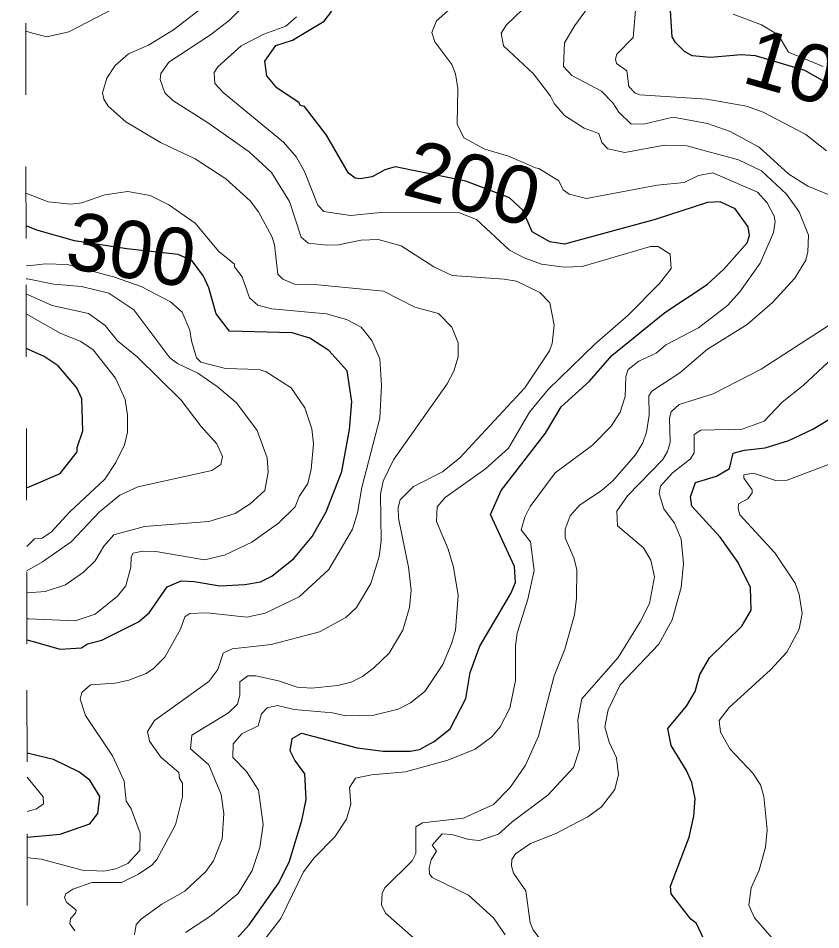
# Model space of a CAD drawing. Extents: x 474.5 to 500, y 7345.7 to 7373.4.
# Drawn here: x 474.546 to 475.665, y 7352.66 to 7353.931 of the extents above; entities that cross this region are included whole.
import ezdxf
from ezdxf.enums import TextEntityAlignment as Align

# ---------------------------------------------------------------- set-up
doc = ezdxf.new("R2010")
doc.units = 0
doc.header["$LTSCALE"] = 0.032
doc.linetypes.add('SHORT_DASHED', pattern=[2.7, 1.5, -1.2])
for name, color, linetype, lineweight in [('1', 7, 'Continuous', 25), ('2', 7, 'Continuous', 13), ('22', 7, 'SHORT_DASHED', 13)]:
    doc.layers.add(name, color=color, linetype=linetype, lineweight=lineweight)
doc.layers.add('61', color=7, linetype='Continuous')

msp = doc.modelspace()

# ---------------------------------------------------------------- linework, layer by layer
at = {"layer": '1'}
for points in [[(474.9417, 7352.8127), (474.9474, 7352.8417), (474.9458, 7352.8779), (474.9316, 7352.8968), (474.9253, 7352.9095), (474.9281, 7352.9267), (474.9413, 7352.9342), (475.0188, 7352.9139), (475.055, 7352.9091), (475.0929, 7352.9091), (475.1056, 7352.9116), (475.1259, 7352.9225), (475.1484, 7352.9402), (475.17, 7352.9825), (475.1763, 7353.0188), (475.1898, 7353.0555), (475.233, 7353.1292), (475.2393, 7353.1442), (475.2382, 7353.1668), (475.2045, 7353.2393), (475.2193, 7353.2725), (475.2811, 7353.3524), (475.3033, 7353.3893), (475.3426, 7353.4247), (475.374, 7353.4609), (475.4476, 7353.5207), (475.5065, 7353.5598), (475.53, 7353.581), (475.5625, 7353.6177), (475.5656, 7353.6279), (475.5641, 7353.6401), (475.5457, 7353.6653), (475.5247, 7353.6748), (475.5074, 7353.674), (475.4343, 7353.6502), (475.308, 7353.6159), (475.2873, 7353.6191), (475.2627, 7353.633), (475.2496, 7353.663), (475.2311, 7353.6803), (475.1702, 7353.7036), (475.0715, 7353.7234), (475.0575, 7353.7195), (475.0396, 7353.7099), (475.0227, 7353.7069), (475.0158, 7353.7078), (475.0068, 7353.7146), (474.976, 7353.7677), (474.9452, 7353.8079), (474.9394, 7353.8092), (474.9377, 7353.8129), (474.9065, 7353.8339), (474.8926, 7353.8502), (474.89, 7353.8708), (474.9054, 7353.8927), (474.9285, 7353.9), (474.9727, 7353.9268), (474.9836, 7353.9404)], [(475.6815, 7353.836), (475.6429, 7353.8577), (475.5739, 7353.8781), (475.5541, 7353.8798), (475.5114, 7353.876), (475.4857, 7353.8782), (475.475, 7353.8844), (475.4624, 7353.8969), (475.4579, 7353.9049), (475.4556, 7353.941)], [(474.5581, 7353.0644), (474.5671, 7353.0619), (474.6048, 7353.0513), (474.6342, 7353.0533), (474.6428, 7353.059), (474.6625, 7353.0641), (474.7138, 7353.0895), (474.7286, 7353.102), (474.7538, 7353.1381), (474.7733, 7353.1466), (474.7913, 7353.1459), (474.8274, 7353.1397), (474.8622, 7353.1414), (474.8839, 7353.1453), (474.8998, 7353.1533), (474.9303, 7353.1777), (474.9558, 7353.2084), (474.9755, 7353.2429), (474.9974, 7353.2992), (475.0081, 7353.3577), (475.0112, 7353.3959), (475.0049, 7353.4393), (474.9791, 7353.4676), (474.9525, 7353.4849), (474.9282, 7353.4922), (474.8406, 7353.4945), (474.8222, 7353.5186), (474.8121, 7353.5549), (474.8046, 7353.5712), (474.7886, 7353.5927), (474.7691, 7353.6015), (474.6974, 7353.6095), (474.6246, 7353.6204), (474.572, 7353.6353), (474.5574, 7353.6415), (474.5571, 7353.6416)], [(474.5577, 7353.2763), (474.5645, 7353.2792), (474.6046, 7353.2962), (474.6283, 7353.3265), (474.6284, 7353.3326), (474.6363, 7353.3558), (474.6347, 7353.4004), (474.628, 7353.4154), (474.6018, 7353.4461), (474.5824, 7353.4593), (474.5606, 7353.4691), (474.5574, 7353.4706)], [(475.5019, 7352.6471), (475.4919, 7352.669), (475.484, 7352.675), (475.4563, 7352.7103), (475.4556, 7352.721), (475.4816, 7352.7896), (475.4879, 7352.8186), (475.49, 7352.8434), (475.4854, 7352.8656), (475.4778, 7352.8822), (475.4563, 7352.9173), (475.4517, 7352.9407), (475.4778, 7352.9718), (475.4898, 7352.9926), (475.4963, 7353.0162), (475.5102, 7353.0392), (475.5551, 7353.0835), (475.5681, 7353.1057), (475.5672, 7353.1372), (475.5499, 7353.1721), (475.5248, 7353.2077), (475.4853, 7353.2506), (475.4836, 7353.2635), (475.4903, 7353.2839), (475.5196, 7353.2925), (475.5377, 7353.3032), (475.5431, 7353.3247), (475.5589, 7353.3288), (475.5875, 7353.3319), (475.6204, 7353.3421), (475.654, 7353.358), (475.6834, 7353.3758)], [(474.5586, 7352.7894), (474.5637, 7352.7898), (474.6047, 7352.7934), (474.6458, 7352.8078), (474.657, 7352.8222), (474.6601, 7352.846), (474.646, 7352.8689), (474.6305, 7352.8805), (474.5951, 7352.8977), (474.5606, 7352.9059), (474.5584, 7352.9064)], [(474.8414, 7352.6378), (474.8682, 7352.6671), (474.9093, 7352.7258), (474.9243, 7352.7561), (474.9417, 7352.8127)]]:
    msp.add_lwpolyline(points, dxfattribs=at)
at = {"layer": '2'}
for points in [[(475.6903, 7353.679), (475.6472, 7353.6967), (475.6205, 7353.7135), (475.579, 7353.7508), (475.5388, 7353.7729), (475.5072, 7353.7839), (475.4591, 7353.7928), (475.42, 7353.7834), (475.4009, 7353.783), (475.3835, 7353.7996), (475.375, 7353.8129), (475.3596, 7353.829), (475.3179, 7353.8511), (475.3064, 7353.8635), (475.308, 7353.8963), (475.3223, 7353.9206), (475.364, 7353.9783)], [(474.7082, 7352.6535), (474.7105, 7352.6678), (474.718, 7352.6757), (474.7462, 7352.6959), (474.7783, 7352.7142), (474.8077, 7352.7414), (474.8185, 7352.7563), (474.8307, 7352.7869), (474.8326, 7352.8223), (474.8292, 7352.849), (474.8121, 7352.8901), (474.7863, 7352.9125), (474.7881, 7352.9314), (474.8395, 7352.9629), (474.8518, 7352.9747), (474.8549, 7352.9872), (474.855, 7353.0061), (474.8663, 7353.0143), (474.8772, 7353.0143), (474.9089, 7353.0072), (474.935, 7352.9985), (474.9548, 7352.9969), (474.9919, 7353.0008), (475.0102, 7353.0055), (475.0262, 7353.0134), (475.0415, 7353.0247), (475.0635, 7353.0458), (475.0822, 7353.0781), (475.0917, 7353.1096), (475.0942, 7353.1335), (475.0903, 7353.1657), (475.0765, 7353.2338), (475.0759, 7353.2489), (475.0786, 7353.2597), (475.0972, 7353.2783), (475.1377, 7353.2984), (475.1618, 7353.3182), (475.2524, 7353.4156), (475.2871, 7353.4672), (475.2905, 7353.4773), (475.2936, 7353.5031), (475.2872, 7353.5343), (475.2734, 7353.5485), (475.2408, 7353.5641), (475.2237, 7353.5672), (475.1511, 7353.5721), (475.1258, 7353.5842), (475.0801, 7353.6133), (475.0482, 7353.6222), (475.0243, 7353.6215), (474.9927, 7353.6151), (474.977, 7353.6143), (474.9504, 7353.6173), (474.9408, 7353.6258), (474.9242, 7353.6752), (474.8993, 7353.7157), (474.8682, 7353.7445), (474.8116, 7353.7843), (474.7617, 7353.8159), (474.7504, 7353.8266), (474.7441, 7353.8454), (474.745, 7353.8539), (474.7561, 7353.8697), (474.8141, 7353.9074), (474.8409, 7353.9282), (474.8784, 7353.9657)], [(474.9586, 7352.7606), (474.9877, 7352.7898), (475.0039, 7352.8147), (475.0098, 7352.8355), (475.0081, 7352.8584), (475.0163, 7352.8715), (475.0386, 7352.8764), (475.086, 7352.8803), (475.145, 7352.8969), (475.1833, 7352.9121), (475.2063, 7352.9294), (475.218, 7352.9433), (475.2315, 7352.9694), (475.2394, 7353.0077), (475.2395, 7353.0561), (475.2419, 7353.0737), (475.2569, 7353.1213), (475.2657, 7353.1611), (475.2602, 7353.2008), (475.2475, 7353.2178), (475.2525, 7353.2354), (475.26, 7353.2503), (475.2948, 7353.2971), (475.347, 7353.3356), (475.3728, 7353.3624), (475.3853, 7353.3819), (475.3925, 7353.4036), (475.3932, 7353.4314), (475.3964, 7353.441), (475.4113, 7353.4529), (475.4354, 7353.4641), (475.4489, 7353.4757), (475.4945, 7353.4992), (475.5351, 7353.5304), (475.5522, 7353.5493), (475.5807, 7353.5893), (475.5992, 7353.6319), (475.6014, 7353.6472), (475.6, 7353.6547), (475.5904, 7353.6733), (475.577, 7353.6883), (475.5144, 7353.7154), (475.4947, 7353.7115), (475.4746, 7353.7018), (475.437, 7353.698), (475.3386, 7353.6797), (475.3142, 7353.6854), (475.306, 7353.6914), (475.2999, 7353.7043), (475.2721, 7353.7211), (475.2673, 7353.722), (475.2299, 7353.7387), (475.1969, 7353.7483), (475.1676, 7353.7638), (475.1581, 7353.7829), (475.1589, 7353.8327), (475.1557, 7353.8534), (475.1508, 7353.8663), (475.1272, 7353.8978), (475.123, 7353.9108), (475.1295, 7353.9272), (475.1795, 7353.9715)], [(475.2827, 7353.9756), (475.2268, 7353.9216), (475.2195, 7353.9099), (475.2226, 7353.8921), (475.2648, 7353.853), (475.2885, 7353.8222), (475.2932, 7353.8117), (475.308, 7353.7953), (475.3352, 7353.7775), (475.3556, 7353.7699), (475.36, 7353.7577), (475.3682, 7353.7488), (475.3918, 7353.7436), (475.4471, 7353.7539), (475.4785, 7353.7531), (475.5503, 7353.7332), (475.5824, 7353.7179), (475.6174, 7353.6853), (475.635, 7353.6607), (475.6478, 7353.6286), (475.6471, 7353.605), (475.6442, 7353.5936), (475.6291, 7353.5685), (475.5977, 7353.5345), (475.5623, 7353.504), (475.5071, 7353.4694), (475.4687, 7353.4364), (475.4297, 7353.4112), (475.4253, 7353.4043)], [(474.5566, 7353.9126), (474.5659, 7353.9101), (474.5861, 7353.9047), (474.6169, 7353.9118), (474.6937, 7353.9517)], [(474.6132, 7352.6986), (474.6108, 7352.7052), (474.6126, 7352.7106), (474.6222, 7352.7169), (474.6488, 7352.7262), (474.6903, 7352.7264), (474.714, 7352.738), (474.7322, 7352.7505), (474.7392, 7352.7582), (474.7653, 7352.8064), (474.7752, 7352.8455), (474.775, 7352.8648), (474.7708, 7352.8711), (474.7702, 7352.8794), (474.745, 7352.9008), (474.729, 7352.9232), (474.7265, 7352.9367), (474.7359, 7352.952), (474.812, 7353.0065), (474.8246, 7353.0232), (474.8319, 7353.046), (474.8443, 7353.0521), (474.8986, 7353.058), (474.9663, 7353.0756), (475.0028, 7353.0954), (475.018, 7353.1096), (475.0379, 7353.143), (475.0496, 7353.1806), (475.052, 7353.2026), (475.0512, 7353.2674), (475.055, 7353.2854), (475.0692, 7353.3152), (475.1443, 7353.421), (475.1534, 7353.4388), (475.1595, 7353.459), (475.1597, 7353.4781), (475.1509, 7353.5), (475.132, 7353.5194), (475.099, 7353.5281), (475.0556, 7353.5504), (474.964, 7353.5592), (474.9312, 7353.5601), (474.9152, 7353.5671), (474.9082, 7353.5741), (474.9035, 7353.6147), (474.9003, 7353.6254), (474.8811, 7353.6607), (474.8696, 7353.6761), (474.8355, 7353.707), (474.7929, 7353.7346), (474.7443, 7353.7573), (474.6961, 7353.7863), (474.6716, 7353.808), (474.6654, 7353.818), (474.6635, 7353.8267), (474.6698, 7353.8471), (474.6811, 7353.8649), (474.6999, 7353.8813), (474.7278, 7353.893), (474.7627, 7353.9147), (474.7972, 7353.9412)], [(475.4068, 7353.942), (475.4037, 7353.904), (475.3807, 7353.8807), (475.379, 7353.8735), (475.3805, 7353.8676), (475.3948, 7353.8575), (475.3974, 7353.8354), (475.4063, 7353.8265), (475.4128, 7353.8241), (475.5061, 7353.8177), (475.5615, 7353.8082), (475.5846, 7353.8), (475.6441, 7353.7689), (475.6732, 7353.7461)], [(474.934, 7353.9326), (474.9193, 7353.9197), (474.8884, 7353.9086), (474.857, 7353.8922), (474.8244, 7353.8629), (474.8191, 7353.8549), (474.8201, 7353.8397), (474.8318, 7353.8273), (474.9162, 7353.7579), (474.9341, 7353.7371), (474.9454, 7353.7171), (474.964, 7353.6704), (474.9721, 7353.6615), (475.0094, 7353.6558), (475.0515, 7353.6598), (475.1615, 7353.6597), (475.1851, 7353.6501), (475.2313, 7353.6077), (475.2515, 7353.597), (475.2759, 7353.588), (475.3071, 7353.584), (475.3325, 7353.5848), (475.4276, 7353.6126), (475.4384, 7353.6127)], [(475.5431, 7353.9362), (475.5827, 7353.9213), (475.6055, 7353.9078), (475.6201, 7353.8832), (475.6684, 7353.8633)], [(474.5586, 7352.7609), (474.5642, 7352.7603), (474.5781, 7352.7589), (474.6358, 7352.7432), (474.6656, 7352.7419), (474.6821, 7352.7454), (474.6989, 7352.7528), (474.7157, 7352.7708), (474.716, 7352.7952), (474.7036, 7352.8287), (474.6968, 7352.8394), (474.6938, 7352.8673), (474.6776, 7352.9028), (474.6401, 7352.959), (474.6324, 7352.9819), (474.6348, 7352.9911), (474.6471, 7353.0017), (474.6812, 7353.004), (474.7004, 7353.008), (474.7244, 7353.0177), (474.7349, 7353.0244), (474.7506, 7353.0403), (474.7725, 7353.0792), (474.7786, 7353.0964), (474.7854, 7353.1009), (474.8092, 7353.1021), (474.865, 7353.0958), (474.8903, 7353.1014), (474.9376, 7353.1243), (474.9791, 7353.1625), (475.012, 7353.2185), (475.019, 7353.2416), (475.0254, 7353.2767), (475.0503, 7353.3733), (475.0528, 7353.419), (475.0504, 7353.4558), (475.0391, 7353.4818), (475.0242, 7353.5), (475.0039, 7353.5109), (474.9759, 7353.5186), (474.8995, 7353.5257), (474.8803, 7353.5307), (474.8684, 7353.5411), (474.8584, 7353.5704), (474.8478, 7353.5842), (474.8477, 7353.5878), (474.8258, 7353.6058), (474.7926, 7353.6453), (474.7562, 7353.6708), (474.7299, 7353.6838), (474.6991, 7353.6892), (474.6669, 7353.6845), (474.635, 7353.6734), (474.6196, 7353.6718), (474.5877, 7353.6747), (474.5606, 7353.6853), (474.557, 7353.6867)], [(475.4384, 7353.6127), (475.4549, 7353.6021), (475.4564, 7353.5818), (475.4404, 7353.5608), (475.3967, 7353.5171), (475.3499, 7353.4766), (475.285, 7353.4134), (475.2592, 7353.3819), (475.2297, 7353.3317), (475.1975, 7353.3028), (475.1416, 7353.2628), (475.1303, 7353.2498), (475.1294, 7353.2292), (475.1457, 7353.1907), (475.1532, 7353.1659), (475.1596, 7353.1263), (475.1556, 7353.0781), (475.1509, 7353.0603), (475.138, 7353.0301), (475.1131, 7352.9926), (475.0929, 7352.9765), (475.0759, 7352.9676), (475.0421, 7352.9594), (475.0027, 7352.9586), (474.9841, 7352.9625), (474.9309, 7352.9673), (474.9075, 7352.9728), (474.893, 7352.9695), (474.8852, 7352.9614), (474.8808, 7352.9447), (474.8579, 7352.9335), (474.8456, 7352.9195), (474.8453, 7352.9005), (474.8646, 7352.8809), (474.8811, 7352.8551), (474.8876, 7352.807), (474.8828, 7352.7751), (474.8723, 7352.7429), (474.8529, 7352.7108), (474.8148, 7352.68), (474.7795, 7352.6565)], [(474.558, 7353.0939), (474.5611, 7353.0938), (474.6254, 7353.091), (474.6536, 7353.1004), (474.6843, 7353.1254), (474.696, 7353.1398), (474.7033, 7353.1659), (474.7034, 7353.1799), (474.7064, 7353.1852), (474.7192, 7353.1882), (474.7382, 7353.1875), (474.806, 7353.1757), (474.8339, 7353.1825), (474.8719, 7353.2007), (474.9088, 7353.2269), (474.9322, 7353.2498), (474.938, 7353.2643), (474.95, 7353.2823), (474.9547, 7353.3021), (474.9579, 7353.3376), (474.9555, 7353.3587), (474.9457, 7353.3879), (474.9267, 7353.4156), (474.8916, 7353.4379), (474.882, 7353.4411), (474.8351, 7353.4426), (474.8007, 7353.4516), (474.7949, 7353.4576), (474.7875, 7353.4812), (474.7854, 7353.4962), (474.7749, 7353.5211), (474.7582, 7353.5353), (474.7175, 7353.5569), (474.6788, 7353.5703), (474.6145, 7353.5875), (474.5841, 7353.5885), (474.5636, 7353.5862), (474.5572, 7353.5855)], [(474.558, 7353.13), (474.5589, 7353.1301), (474.5839, 7353.1317), (474.6121, 7353.1411), (474.6373, 7353.1589), (474.6534, 7353.1744), (474.6654, 7353.1951), (474.6794, 7353.2106), (474.7222, 7353.2225), (474.8118, 7353.2294), (474.8486, 7353.2406), (474.8695, 7353.2538), (474.8899, 7353.2724), (474.8947, 7353.2983), (474.893, 7353.3181), (474.8795, 7353.356), (474.8505, 7353.3946), (474.8235, 7353.4174), (474.7964, 7353.436), (474.7681, 7353.4493), (474.7574, 7353.4572), (474.7071, 7353.5243), (474.6725, 7353.5474), (474.6342, 7353.5569), (474.5959, 7353.5601), (474.559, 7353.5673), (474.5572, 7353.5677)], [(474.5579, 7353.1606), (474.58, 7353.1731), (474.6201, 7353.2009), (474.6596, 7353.2427), (474.6876, 7353.2658), (474.7129, 7353.2776), (474.8159, 7353.3003), (474.8284, 7353.3087), (474.8308, 7353.3197), (474.8229, 7353.3374), (474.801, 7353.3617), (474.7731, 7353.3985), (474.7119, 7353.4589), (474.6847, 7353.4812), (474.6673, 7353.5026), (474.6442, 7353.5193), (474.5936, 7353.5302), (474.559, 7353.5457), (474.5572, 7353.5465)], [(474.5573, 7353.5189), (474.6047, 7353.492), (474.6333, 7353.4801), (474.6504, 7353.4684), (474.6817, 7353.4291), (474.6952, 7353.3993), (474.6986, 7353.3775), (474.6985, 7353.354), (474.6944, 7353.3364), (474.6823, 7353.3115), (474.6669, 7353.2883), (474.6178, 7353.2424), (474.5926, 7353.2147), (474.5794, 7353.2059), (474.5687, 7353.205), (474.5622, 7353.1987), (474.5579, 7353.1945)], [(475.2251, 7352.6535), (475.209, 7352.677), (475.1738, 7352.7087), (475.1233, 7352.7334), (475.1196, 7352.7385), (475.119, 7352.7466), (475.1218, 7352.7579), (475.1291, 7352.77), (475.1232, 7352.7784), (475.1374, 7352.794), (475.1507, 7352.7932), (475.1743, 7352.7862), (475.1891, 7352.7846), (475.2156, 7352.7935), (475.2346, 7352.8109), (475.2845, 7352.848), (475.3205, 7352.8865), (475.3287, 7352.9122), (475.3265, 7352.953), (475.3319, 7352.9822), (475.3826, 7353.04), (475.4135, 7353.0896), (475.4261, 7353.1151), (475.4332, 7353.152), (475.4284, 7353.1755), (475.4179, 7353.1924), (475.3816, 7353.2235), (475.3807, 7353.2438), (475.3955, 7353.2652), (475.445, 7353.3157), (475.4515, 7353.3268), (475.4549, 7353.3393), (475.4541, 7353.3733), (475.4566, 7353.3821), (475.4678, 7353.3925), (475.5152, 7353.4071), (475.5822, 7353.4418), (475.715, 7353.5275)], [(475.6891, 7353.4641), (475.6406, 7353.4189), (475.6114, 7353.3958), (475.5863, 7353.3693), (475.5556, 7353.3582), (475.4981, 7353.3565), (475.4887, 7353.3505), (475.4884, 7353.3252), (475.4833, 7353.3168), (475.4577, 7353.2965), (475.4415, 7353.2785), (475.4397, 7353.2683), (475.4462, 7353.2471), (475.461, 7353.2268), (475.4706, 7353.2045), (475.4739, 7353.171), (475.4707, 7353.1372), (475.4579, 7353.0925), (475.4391, 7353.0584), (475.3856, 7353.0017), (475.3687, 7352.9668), (475.364, 7352.9431), (475.3702, 7352.9218), (475.3804, 7352.9), (475.383, 7352.8769), (475.3782, 7352.8559), (475.3592, 7352.8318), (475.3401, 7352.8179), (475.295, 7352.794), (475.2604, 7352.7808), (475.2393, 7352.7661), (475.2345, 7352.7581), (475.2339, 7352.7493), (475.2365, 7352.7394), (475.2539, 7352.7146), (475.2601, 7352.67), (475.264, 7352.6604), (475.3039, 7352.6062)], [(475.4253, 7353.4043), (475.426, 7353.3776), (475.4221, 7353.354), (475.4169, 7353.3391), (475.4069, 7353.3224), (475.3752, 7353.2858), (475.3588, 7353.2719), (475.3287, 7353.252), (475.3156, 7353.2374), (475.3089, 7353.2188), (475.3089, 7353.2066), (475.3208, 7353.1785), (475.3248, 7353.1625), (475.3247, 7353.1223), (475.3216, 7353.0992), (475.3081, 7353.0513), (475.2932, 7353.0144), (475.2714, 7352.9301), (475.2536, 7352.8897), (475.2321, 7352.8588), (475.2087, 7352.8347), (475.1672, 7352.8159), (475.11, 7352.8093), (475.1003, 7352.8039), (475.1006, 7352.7665), (475.0956, 7352.7565), (475.0574, 7352.7189), (475.0535, 7352.711), (475.0528, 7352.695), (475.0583, 7352.6834), (475.1091, 7352.6388)], [(475.7067, 7353.3205), (475.6182, 7353.2869), (475.6018, 7353.2867), (475.5712, 7353.2967), (475.558, 7353.2944), (475.5578, 7353.2896), (475.5695, 7353.2735), (475.5696, 7353.2691), (475.5633, 7353.2609), (475.5506, 7353.2541), (475.5498, 7353.2471), (475.5523, 7353.2384), (475.6011, 7353.1855), (475.6295, 7353.1436), (475.6352, 7353.1274), (475.6391, 7353.101), (475.6349, 7353.0792), (475.6177, 7353.0471), (475.5948, 7353.0227), (475.5373, 7352.97), (475.5235, 7352.9518), (475.5251, 7352.9359), (475.5387, 7352.912), (475.5704, 7352.8787), (475.5809, 7352.8625), (475.5857, 7352.8463), (475.5904, 7352.7995), (475.5881, 7352.7756), (475.5793, 7352.7434), (475.5679, 7352.7187), (475.565, 7352.6948), (475.5726, 7352.6769), (475.6128, 7352.6309)], [(474.5585, 7352.8251), (474.5598, 7352.8255), (474.5716, 7352.8288), (474.5812, 7352.836), (474.5811, 7352.8454), (474.5622, 7352.8684), (474.5584, 7352.873)], [(474.8901, 7352.6473), (474.9123, 7352.6761), (474.9441, 7352.7413), (474.9586, 7352.7606)], [(474.625, 7352.6588), (474.618, 7352.6685), (474.6188, 7352.6759), (474.626, 7352.6834), (474.6267, 7352.6878), (474.6132, 7352.6986)]]:
    msp.add_lwpolyline(points, dxfattribs=at)
at = {"layer": '22'}
msp.add_lwpolyline([(474.5591, 7352.4942), (474.5581, 7353.059), (474.5571, 7353.6239), (474.5561, 7354.1888), (474.5551, 7354.7537), (474.5541, 7355.3185), (474.5531, 7355.8834), (474.5521, 7356.4483), (474.5511, 7357.0132), (474.5501, 7357.578), (474.5491, 7358.1429), (474.5481, 7358.7078), (474.5471, 7359.2727), (474.5461, 7359.8375)], dxfattribs=at)

# ---------------------------------------------------------------- texts
at = {"layer": '61', "width": 1.05}
for s, rotation, p in [('100', 343.951, (475.6428, 7353.8161)), ('200', 345.61, (475.1702, 7353.6622))]:
    msp.add_text(s, height=0.08, rotation=rotation, dxfattribs=at).set_placement(p, align=Align.CENTER)
at = {"layer": '61'}
msp.add_text('300', height=0.08, rotation=350.886, dxfattribs=at).set_placement((474.6975, 7353.5689), align=Align.CENTER)

doc.saveas('drawing.dxf')
